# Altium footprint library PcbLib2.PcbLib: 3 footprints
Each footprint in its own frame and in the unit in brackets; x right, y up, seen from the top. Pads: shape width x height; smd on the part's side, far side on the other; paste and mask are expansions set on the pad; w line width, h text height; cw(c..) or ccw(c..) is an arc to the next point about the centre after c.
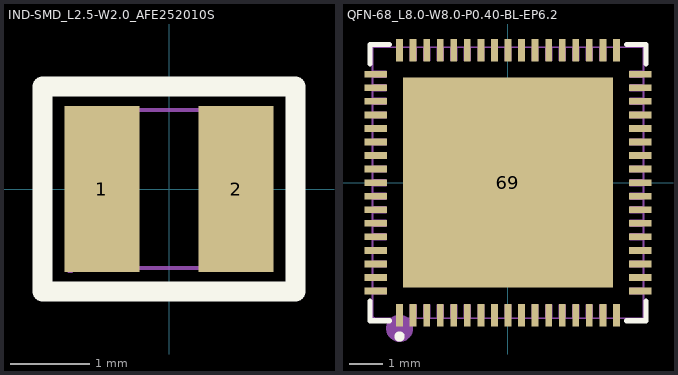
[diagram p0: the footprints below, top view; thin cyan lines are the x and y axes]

## IND-SMD_L2.5-W2.0_AFE252010S [mm]
pads (2):
  rect 0.95x2.1 smd: 1(-0.85,0) 2(0.85,0)
Top Overlay:
  lines w0.254: -1.6,-1.3 -1.6,1.3 1.6,1.3 1.6,-1.3 -1.6,-1.3
Mechanical 6:
  lines w0.051: -1.25,-1 1.25,-1 1.25,1 -1.25,1 -1.25,-1
Mechanical 8:
  region: -1.19,-1 -1.19,-1.025 -1.225,-1.06 -1.275,-1.06 -1.31,-1.025 -1.31,-1 -1.31,-0.975 -1.275,-0.94 -1.225,-0.94 -1.19,-0.975 -1.19,-1
Mechanical 9:
  region: 0.45,1 1.25,1 1.25,-1 0.45,-1
  region: -1.25,1 -0.45,1 -0.45,-1 -1.25,-1

## PCBComponent_1 [mm]

## QFN-68_L8.0-W8.0-P0.40-BL-EP6.2 [mm]
pads (69):
  rect 0.2x0.665 smd paste-100 mask+0.051: 1(-3.2,-3.908) 2(-2.8,-3.908) 3(-2.4,-3.908) 4(-2,-3.908) 5(-1.6,-3.908) 6(-1.2,-3.908) 7(-0.8,-3.908) 8(-0.4,-3.908) 9(0,-3.908) 10(0.4,-3.908) 11(0.8,-3.908) 12(1.2,-3.908) 13(1.6,-3.908) 14(2,-3.908) 15(2.4,-3.908) 16(2.8,-3.908) 17(3.2,-3.908) 35(3.2,3.908) 36(2.8,3.908) 37(2.4,3.908) 38(2,3.908) 39(1.6,3.908) 40(1.2,3.908) 41(0.8,3.908) 42(0.4,3.908) 43(0,3.908) 44(-0.4,3.908) 45(-0.8,3.908) 46(-1.2,3.908) 47(-1.6,3.908) 48(-2,3.908) 49(-2.4,3.908) 50(-2.8,3.908) 51(-3.2,3.908)
  rect 0.665x0.2 smd paste-100 mask+0.051: 18(3.908,-3.2) 19(3.908,-2.8) 20(3.908,-2.4) 21(3.908,-2) 22(3.908,-1.6) 23(3.908,-1.2) 24(3.908,-0.8) 25(3.908,-0.4) 26(3.908,0) 27(3.908,0.4) 28(3.908,0.8) 29(3.908,1.2) 30(3.908,1.6) 31(3.908,2) 32(3.908,2.4) 33(3.908,2.8) 34(3.908,3.2) 52(-3.908,3.2) 53(-3.908,2.8) 54(-3.908,2.4) 55(-3.908,2) 56(-3.908,1.6) 57(-3.908,1.2) 58(-3.908,0.8) 59(-3.908,0.4) 60(-3.908,0) 61(-3.908,-0.4) 62(-3.908,-0.8) 63(-3.908,-1.2) 64(-3.908,-1.6) 65(-3.908,-2) 66(-3.908,-2.4) 67(-3.908,-2.8) 68(-3.908,-3.2)
  rect 6.2x6.2 smd paste-100 mask+0.051: 69(0,0)
Top Overlay:
  circle w0.15: c-3.2,-4.54 r0.075
  lines w0.152: -4.076,-3.503 -4.076,-4.076 -3.503,-4.076 ; -4.076,3.503 -4.076,4.076 -3.503,4.076 ; 3.503,-4.076 4.076,-4.076 4.076,-3.503 ; 3.503,4.076 4.076,4.076 4.076,3.503
Top Paste:
  drawing of 69 lines, arcs and shapes, not listed
Mechanical 2:
  circle w0.4: c-3.2,-4.3 r0.2
Mechanical 6:
  lines w0.051: -4,-4 -4,4 4,4 4,-4 -4,-4
Mechanical 8:
  region: -3.94,-4 -3.94,-4.025 -3.975,-4.06 -4.025,-4.06 -4.06,-4.025 -4.06,-4 -4.06,-3.975 -4.025,-3.94 -3.975,-3.94 -3.94,-3.975 -3.94,-4
Mechanical 9:
  drawing of 69 lines, arcs and shapes, not listed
